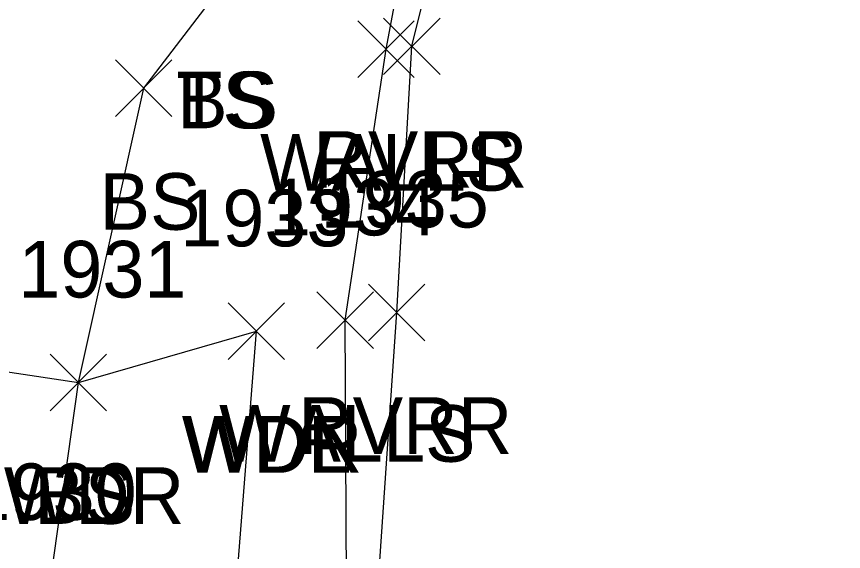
# Model space of a CAD drawing. Extents: x 1461855 to 1464118, y 556196 to 557441.
# Drawn here: x 1462136.67 to 1462165.93, y 556387.14 to 556406.04 of the extents above; entities that cross this region are included whole.
import ezdxf

# ---------------------------------------------------------------- set-up
doc = ezdxf.new("R2010")
doc.units = 0
for name, color, linetype in [('L_A', 7, 'Continuous'), ('L_I', 7, 'Continuous'), ('L_TIC', 7, 'Continuous'), ('LAWA', 7, 'Continuous'), ('LAWE', 7, 'Continuous'), ('LELB', 7, 'Continuous'), ('LSOGP', 7, 'Continuous'), ('LWS', 7, 'Continuous')]:
    doc.layers.add(name, color=color, linetype=linetype)

msp = doc.modelspace()

# ---------------------------------------------------------------- linework, layer by layer
at = {"layer": 'L_TIC'}
for points in [[(1462148.745, 556403.887), (1462150.745, 556405.887)], [(1462150.745, 556403.887), (1462148.745, 556405.887)], [(1462149.659, 556403.988), (1462151.659, 556405.988)], [(1462151.659, 556403.988), (1462149.659, 556405.988)], [(1462140.172, 556402.505), (1462142.172, 556404.505)], [(1462142.172, 556402.505), (1462140.172, 556404.505)], [(1462149.123, 556394.584), (1462151.123, 556396.584)], [(1462151.123, 556394.584), (1462149.123, 556396.584)], [(1462147.298, 556394.306), (1462149.298, 556396.306)], [(1462149.298, 556394.306), (1462147.298, 556396.306)], [(1462144.159, 556393.919), (1462146.159, 556395.919)], [(1462146.159, 556393.919), (1462144.159, 556395.919)], [(1462144.159, 556393.919), (1462146.159, 556395.919)], [(1462146.159, 556393.919), (1462144.159, 556395.919)], [(1462137.861, 556392.111), (1462139.861, 556394.111)], [(1462139.861, 556392.111), (1462137.861, 556394.111)], [(1462137.861, 556392.111), (1462139.861, 556394.111)], [(1462139.861, 556392.111), (1462137.861, 556394.111)]]:
    msp.add_lwpolyline(points, dxfattribs=at)
at = {"layer": 'LAWA'}
for points in [[(1462103.87, 556357.158), (1462105.529, 556380.621), (1462104.39, 556394.374), (1462118.433, 556400.322), (1462128.676, 556394.64), (1462138.861, 556393.111), (1462145.159, 556394.919)], [(1462152.985, 556347.291), (1462145.87, 556357.355), (1462145.025, 556371.865), (1462144.044, 556380.752), (1462145.159, 556394.919)]]:
    msp.add_lwpolyline(points, dxfattribs=at)
at = {"layer": 'LAWE'}
msp.add_lwpolyline([(1462154.863, 556328.185), (1462154.036, 556339.342), (1462154.572, 556350.205), (1462152.486, 556361.373), (1462151.238, 556373.266), (1462149.161, 556381.463), (1462150.123, 556395.584), (1462150.659, 556404.988), (1462152.286, 556411.553), (1462152.849, 556416.044), (1462153.935, 556421.507), (1462155.971, 556453.801), (1462150.724, 556458.73), (1462147.201, 556465.728), (1462141.304, 556477.136), (1462134.96, 556494.769), (1462123.898, 556516.113), (1462120.543, 556522.084)], dxfattribs=at)
at = {"layer": 'LELB'}
msp.add_lwpolyline([(1462148.367, 556381.382), (1462144.044, 556380.752), (1462137.754, 556385.246), (1462138.861, 556393.111), (1462141.172, 556403.505), (1462143.915, 556407.092), (1462147.378, 556411.884)], dxfattribs=at)
at = {"layer": 'LSOGP'}
msp.add_lwpolyline([(1462020.074, 556368.854), (1462042.956, 556370.973), (1462054.408, 556366.714), (1462057.178, 556367.868), (1462065.942, 556367.888), (1462067.55, 556365.344), (1462103.87, 556357.158), (1462116.955, 556337.28), (1462130.508, 556327.239), (1462142.904, 556324.832), (1462154.863, 556328.185), (1462154.036, 556339.342), (1462154.572, 556350.205), (1462152.486, 556361.373), (1462151.238, 556373.266), (1462149.161, 556381.463), (1462150.123, 556395.584), (1462150.659, 556404.988), (1462152.286, 556411.553), (1462201.558, 556420.694)], dxfattribs=at)
at = {"layer": 'LWS'}
msp.add_lwpolyline([(1462145.025, 556371.865), (1462149.189, 556373.821), (1462148.367, 556381.382), (1462148.298, 556395.306), (1462149.745, 556404.887), (1462151.026, 556411.673), (1462148.839, 556411.931)], dxfattribs=at)

# ---------------------------------------------------------------- texts
at = {"layer": 'L_A'}
for s, p in [('TS', (1462142.324, 556402.092)), ('BS', (1462142.356, 556402.092)), ('WALLS', (1462145.289, 556399.887)), ('RVRR', (1462147.171, 556399.988)), ('BS', (1462139.613, 556398.505)), ('RVRR', (1462146.634, 556390.584)), ('WALLS', (1462143.842, 556390.306)), ('WDR', (1462142.521, 556389.919)), ('WDL', (1462142.576, 556389.919)), ('WDR', (1462136.224, 556388.111)), ('BS', (1462137.302, 556388.111))]:
    msp.add_text(s, height=2, dxfattribs=at).set_placement(p)
at = {"layer": 'L_I'}
for s, p in [('1935', (1462147.43, 556398.584)), ('1934', (1462145.606, 556398.306)), ('1933', (1462142.466, 556397.919)), ('1933', (1462142.466, 556397.919)), ('1931', (1462136.735, 556396.111)), ('1931', (1462136.735, 556396.111)), ('1930', (1462134.974, 556388.246))]:
    msp.add_text(s, height=2, dxfattribs=at).set_placement(p)

doc.saveas('drawing.dxf')
